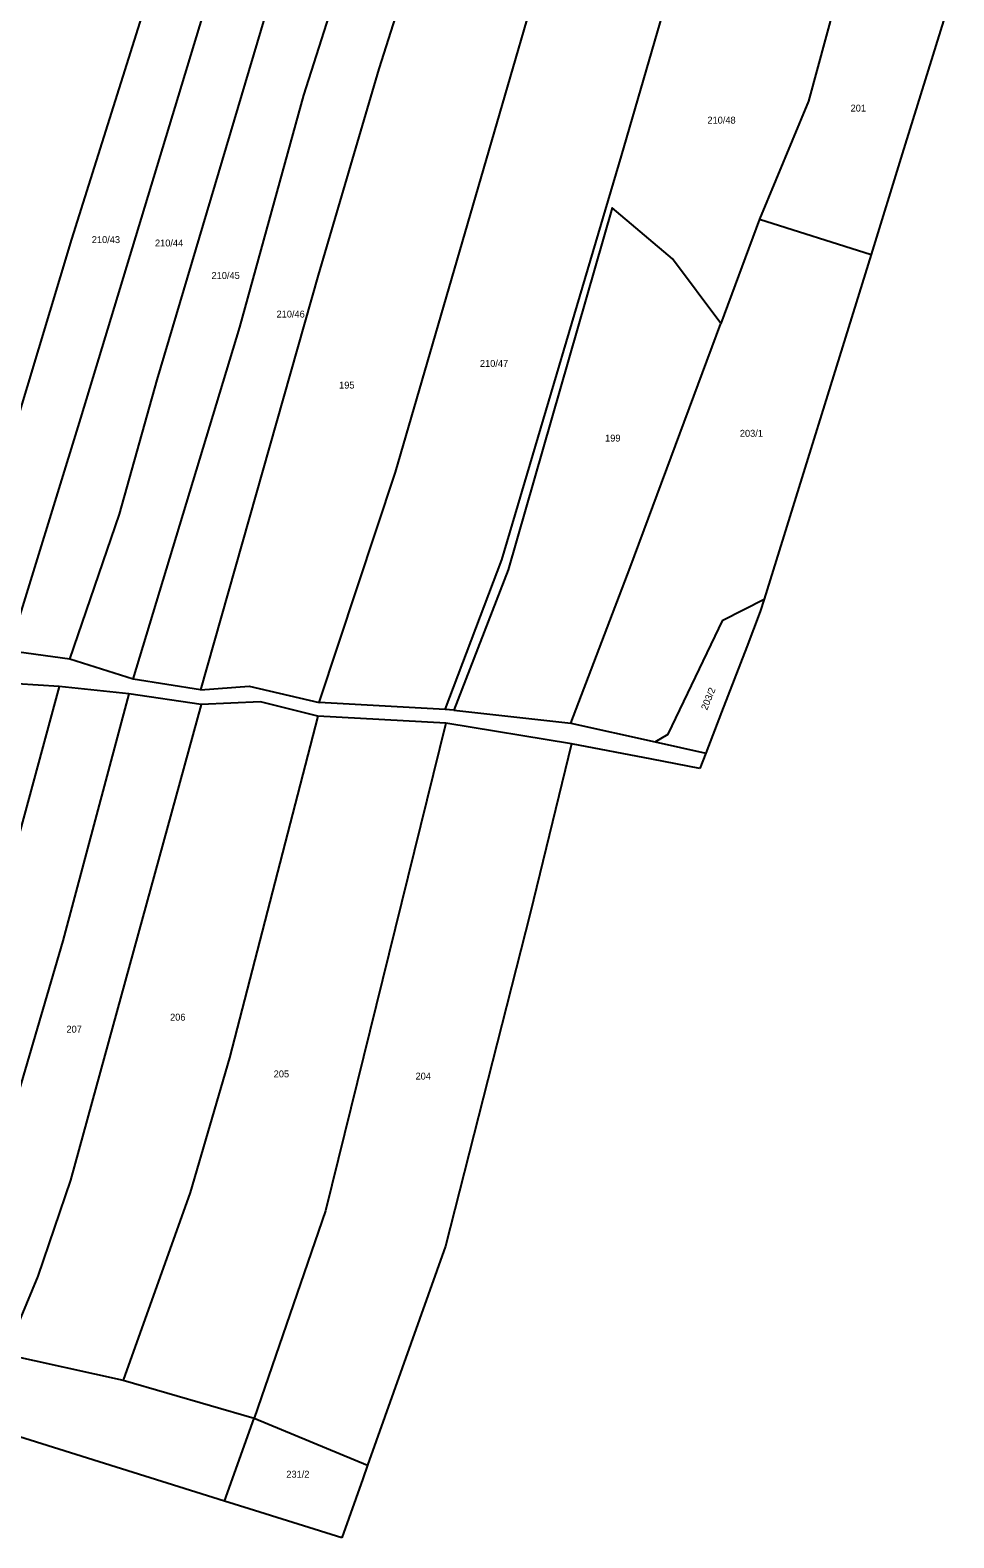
# Model space of a CAD drawing. Extents: x -746176 to -739709, y -1128407 to -1124482.
# Drawn here: x -742474.2 to -742246.8, y -1127907.2 to -1127536.1 of the extents above; entities that cross this region are included whole.
import ezdxf

# ---------------------------------------------------------------- set-up
doc = ezdxf.new("R2010")
doc.units = 0
doc.layers.add('Hranice parcel', color=7, linetype='Continuous')
doc.layers.add('Parcelní čísla', color=7, linetype='Continuous')

msp = doc.modelspace()

# ---------------------------------------------------------------- linework, layer by layer
at = {"layer": 'Hranice parcel'}
for p, q in [((-742246.84, -1127525.71), (-742259.53, -1127566.57)), ((-742259.53, -1127566.57), (-742267.21, -1127591.32)), ((-742294.71, -1127582.66), (-742304.21, -1127608.28)), ((-742294.71, -1127582.66), (-742267.21, -1127591.32)), ((-742267.21, -1127591.32), (-742293.55, -1127676.19)), ((-742294.48, -1127679.19), (-742297.82, -1127687.89)), ((-742293.55, -1127676.19), (-742294.48, -1127679.19)), ((-742464.41, -1127690.97), (-742479.32, -1127688.85)), ((-742297.82, -1127687.89), (-742304, -1127703.97)), ((-742448.8, -1127695.84), (-742464.41, -1127690.97)), ((-742467.04, -1127697.67), (-742483.38, -1127696.63)), ((-742449.94, -1127699.44), (-742467.04, -1127697.67)), ((-742432.3, -1127698.48), (-742448.8, -1127695.84)), ((-742432.12, -1127702.08), (-742449.94, -1127699.44)), ((-742372.01, -1127703.32), (-742403.02, -1127701.6)), ((-742371.88, -1127706.65), (-742403.42, -1127704.93)), ((-742369.9, -1127703.45), (-742372.01, -1127703.32)), ((-742369.9, -1127703.45), (-742341.09, -1127706.66)), ((-742304, -1127703.97), (-742307.87, -1127714.04)), ((-742340.92, -1127711.81), (-742371.88, -1127706.65)), ((-742341.09, -1127706.66), (-742320.38, -1127711.26)), ((-742321.14, -1127715.58), (-742340.92, -1127711.81)), ((-742320.38, -1127711.26), (-742307.87, -1127714.04)), ((-742309.33, -1127717.84), (-742321.14, -1127715.58)), ((-742307.87, -1127714.04), (-742309.33, -1127717.84)), ((-742480.24, -1127862.01), (-742451.26, -1127868.39)), ((-742451.26, -1127868.39), (-742419.07, -1127877.77)), ((-742426.38, -1127898.15), (-742491.5, -1127877.75)), ((-742426.38, -1127898.15), (-742419.07, -1127877.77)), ((-742419.07, -1127877.77), (-742391.12, -1127889.33)), ((-742391.12, -1127889.33), (-742392.3, -1127892.65)), ((-742392.3, -1127892.65), (-742397.46, -1127907.21)), ((-742420.31, -1127900.05), (-742426.38, -1127898.15)), ((-742397.46, -1127907.21), (-742420.31, -1127900.05))]:
    msp.add_line(p, q, dxfattribs=at)
for points in [[(-742494, -1127687.08), (-742463.97, -1127587.54), (-742428.89, -1127476.24)], [(-742479.32, -1127688.85), (-742461.68, -1127631.58), (-742415.87, -1127480.36)], [(-742464.41, -1127690.97), (-742452.19, -1127655.25), (-742442.95, -1127622.18), (-742402.15, -1127485.01)], [(-742448.8, -1127695.84), (-742422.61, -1127609.18), (-742406.86, -1127552.13), (-742387.37, -1127491.14)], [(-742373.12, -1127497.63), (-742388.36, -1127545.64), (-742403.33, -1127596.39), (-742432.3, -1127698.48)], [(-742403.02, -1127701.6), (-742384.25, -1127644.88), (-742343.44, -1127504.37)], [(-742372.01, -1127703.32), (-742358.1, -1127666.45), (-742328.66, -1127567.04), (-742312.99, -1127513.08), (-742313.1, -1127510.34)], [(-742274.2, -1127522.4), (-742282.6, -1127553.63), (-742294.71, -1127582.66)], [(-742304.21, -1127608.28), (-742316.12, -1127592.36), (-742330.9, -1127579.81), (-742356.55, -1127668.96), (-742369.9, -1127703.45)], [(-742341.09, -1127706.66), (-742326.47, -1127668.34), (-742304.21, -1127608.28)], [(-742320.38, -1127711.26), (-742317.14, -1127709.37), (-742303.66, -1127681.35), (-742293.55, -1127676.19)], [(-742467.04, -1127697.67), (-742480.9, -1127748.82), (-742494.32, -1127803.6), (-742511.96, -1127847.84)], [(-742432.3, -1127698.48), (-742420.3, -1127697.56), (-742403.02, -1127701.6)], [(-742449.94, -1127699.44), (-742466.13, -1127760.26), (-742485.77, -1127826.93), (-742498.72, -1127857.52)], [(-742403.42, -1127704.93), (-742417.48, -1127701.42), (-742432.12, -1127702.08)], [(-742432.12, -1127702.08), (-742464.27, -1127819.17), (-742472.32, -1127842.8), (-742480.24, -1127862.01)], [(-742403.42, -1127704.93), (-742425.12, -1127789.08), (-742434.82, -1127822.21), (-742451.26, -1127868.39)], [(-742371.88, -1127706.65), (-742401.48, -1127826.73), (-742419.07, -1127877.77)], [(-742340.92, -1127711.81), (-742351.14, -1127753.54), (-742371.99, -1127835.4), (-742391.12, -1127889.33)]]:
    msp.add_lwpolyline(points, dxfattribs=at)

# ---------------------------------------------------------------- texts
at = {"layer": 'Parcelní čísla'}
for s, p in [('201', (-742272.25, -1127556.14)), ('210/48', (-742307.5, -1127559.11)), ('210/43', (-742459.02, -1127588.52)), ('210/44', (-742443.47, -1127589.35)), ('210/45', (-742429.55, -1127597.35)), ('210/46', (-742413.55, -1127606.84)), ('210/47', (-742363.49, -1127618.99)), ('195', (-742398.15, -1127624.33)), ('203/1', (-742299.51, -1127636.19)), ('199', (-742332.68, -1127637.37)), ('206', (-742439.75, -1127779.9)), ('207', (-742465.26, -1127782.86)), ('205', (-742414.25, -1127793.87)), ('204', (-742379.34, -1127794.41)), ('231/2', (-742411.14, -1127892.4))]:
    msp.add_text(s, height=1.7, dxfattribs=at).set_placement(p)
msp.add_text('203/2', height=1.7, rotation=68, dxfattribs=at).set_placement((-742307.58, -1127703.62))

doc.saveas('drawing.dxf')
